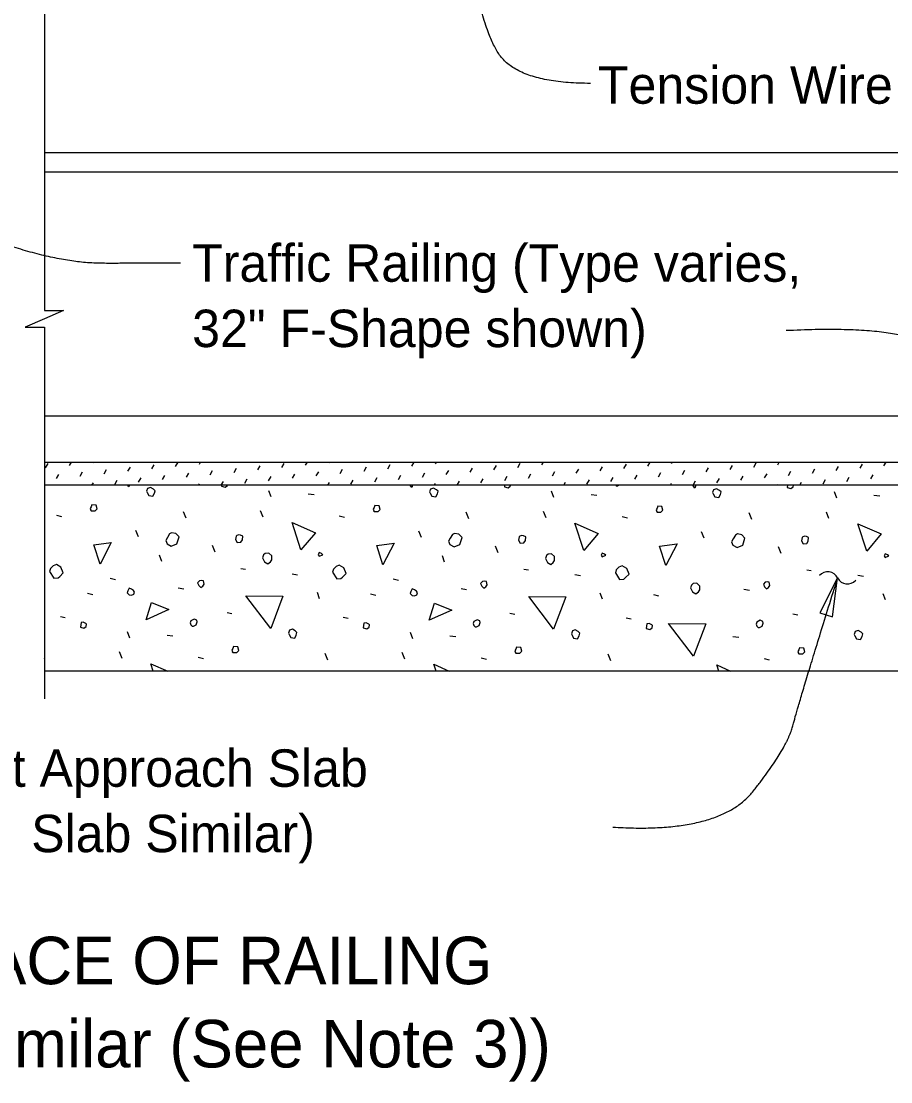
# Model space of a CAD drawing. Extents: x 0 to 41.1, y 0 to 25.9.
# Drawn here: x 16.13 to 20.81, y 11.22 to 16.93 of the extents above; entities that cross this region are included whole.
import ezdxf

# ---------------------------------------------------------------- set-up
doc = ezdxf.new("R2010")
doc.units = 0
for name, color, linetype in [('Dimension', 7, 'Continuous'), ('Miscellaneous', 7, 'Continuous'), ('SupstrConc', 7, 'Continuous'), ('SupstrConc_h', 7, 'Continuous'), ('TextStructures', 7, 'Continuous')]:
    doc.layers.add(name, color=color, linetype=linetype)

msp = doc.modelspace()

# ---------------------------------------------------------------- linework, layer by layer
at = {"layer": 'Dimension'}
msp.add_lwpolyline([(16.252, 17.2246), (16.252, 15.3737), (16.3553, 15.3737), (16.252, 15.3287), (16.1487, 15.2837), (16.252, 15.2837), (16.252, 13.2829)], dxfattribs=at)
msp.add_lwpolyline([(20.5246, 13.9338), (20.4289, 13.7455), (20.4962, 13.7245)], close=True, dxfattribs=at)
for centre, start, end in [((20.4706, 13.907), 26.8413, 138.5686), ((20.577, 13.9608), 206.8413, 318.5686)]:
    msp.add_arc(centre, 0.0596, start, end, dxfattribs=at)
for points in [[(19.1927, 16.5972), (18.7949, 16.5972), (18.5909, 16.9342), (18.5297, 17.3911)], [(16.9853, 15.6282), (16.9154, 15.6282), (16.2159, 15.6282), (15.6583, 15.8852)], [(20.2473, 15.2675), (20.836, 15.2958), (21.1574, 15.0877), (21.234, 15.0765)], [(19.3131, 12.5922), (19.886, 12.5557), (20.2509, 13.0124), (20.3172, 13.2697), (20.5245, 13.9337)]]:
    msp.add_open_spline(points, degree=2, dxfattribs=at)
at = {"layer": 'Miscellaneous'}
for p, q in [((16.2587, 14.5271), (16.2717, 14.5495)), ((16.3872, 14.5401), (16.3975, 14.5578)), ((16.5157, 14.5531), (16.5184, 14.5578)), ((16.5734, 14.4953), (16.5864, 14.5177)), ((16.7019, 14.5083), (16.7148, 14.5307)), ((16.8303, 14.5212), (16.8433, 14.5436)), ((16.9588, 14.5342), (16.9717, 14.5566)), ((17.0872, 14.5472), (17.0934, 14.5578)), ((17.145, 14.4894), (17.1579, 14.5118)), ((17.2734, 14.5024), (17.2864, 14.5248)), ((17.4019, 14.5154), (17.4149, 14.5377)), ((17.5303, 14.5283), (17.5433, 14.5507)), ((17.6588, 14.5413), (17.6684, 14.5578)), ((17.7873, 14.5542), (17.7893, 14.5578)), ((17.845, 14.4965), (17.858, 14.5189)), ((17.9735, 14.5095), (17.9864, 14.5318)), ((18.1019, 14.5224), (18.1149, 14.5448)), ((18.2304, 14.5354), (18.2433, 14.5578)), ((18.3588, 14.5483), (18.3643, 14.5578)), ((18.4166, 14.4906), (18.4296, 14.513)), ((18.545, 14.5036), (18.558, 14.526)), ((18.6735, 14.5165), (18.6865, 14.5389)), ((18.802, 14.5295), (18.8149, 14.5519)), ((18.9304, 14.5425), (18.9393, 14.5578)), ((18.9882, 14.4847), (19.0011, 14.5071)), ((19.0589, 14.5554), (19.0603, 14.5578)), ((19.1166, 14.4977), (19.1296, 14.5201)), ((19.2451, 14.5106), (19.258, 14.533)), ((19.3735, 14.5236), (19.3865, 14.546)), ((19.502, 14.5366), (19.5143, 14.5578)), ((19.6305, 14.5495), (19.6353, 14.5578)), ((19.6882, 14.4918), (19.7012, 14.5142)), ((19.8167, 14.5047), (19.8296, 14.5271)), ((19.9451, 14.5177), (19.9581, 14.5401)), ((20.0736, 14.5307), (20.0865, 14.5531)), ((20.202, 14.5436), (20.2103, 14.5578)), ((20.2598, 14.4859), (20.2727, 14.5083)), ((20.3305, 14.5566), (20.3312, 14.5578)), ((20.3882, 14.4989), (20.4012, 14.5212)), ((20.5167, 14.5118), (20.5297, 14.5342)), ((20.6452, 14.5248), (20.6581, 14.5472)), ((20.7736, 14.5377), (20.7852, 14.5578)), ((16.3165, 14.4694), (16.3294, 14.4918)), ((16.4449, 14.4824), (16.4579, 14.5047)), ((16.6311, 14.4376), (16.6441, 14.46)), ((16.7596, 14.4505), (16.7726, 14.4729)), ((16.8881, 14.4635), (16.901, 14.4859)), ((17.0165, 14.4765), (17.0295, 14.4989)), ((17.2034, 14.4329), (17.2157, 14.4541)), ((17.3312, 14.4446), (17.3441, 14.467)), ((17.4596, 14.4576), (17.4726, 14.48)), ((17.5881, 14.4706), (17.6011, 14.493)), ((17.7166, 14.4835), (17.7295, 14.5059)), ((17.9028, 14.4387), (17.9157, 14.4611)), ((18.0312, 14.4517), (18.0442, 14.4741)), ((18.1597, 14.4647), (18.1726, 14.4871)), ((18.2881, 14.4776), (18.3011, 14.5)), ((18.4743, 14.4329), (18.4873, 14.4552)), ((18.6028, 14.4458), (18.6158, 14.4682)), ((18.7313, 14.4588), (18.7442, 14.4812)), ((18.8597, 14.4717), (18.8727, 14.4941)), ((19.0493, 14.4329), (19.0589, 14.4494)), ((19.1744, 14.4399), (19.1873, 14.4623)), ((19.3028, 14.4529), (19.3158, 14.4753)), ((19.4313, 14.4659), (19.4443, 14.4882)), ((19.5597, 14.4788), (19.5727, 14.5012)), ((19.746, 14.434), (19.7589, 14.4564)), ((19.8744, 14.447), (19.8874, 14.4694)), ((20.0029, 14.46), (20.0158, 14.4824)), ((20.1313, 14.4729), (20.1443, 14.4953)), ((20.3203, 14.4329), (20.3305, 14.4505)), ((20.446, 14.4411), (20.459, 14.4635)), ((20.5744, 14.4541), (20.5874, 14.4765)), ((20.7029, 14.467), (20.7159, 14.4894)), ((16.5075, 14.4329), (16.5157, 14.447)), ((17.0825, 14.4329), (17.0872, 14.4411)), ((17.4727, 14.3704), (17.4603, 14.404)), ((17.6574, 14.4329), (17.6588, 14.4352)), ((17.7784, 14.4329), (17.7873, 14.4482)), ((18.3534, 14.4329), (18.3588, 14.4423)), ((18.9965, 14.3669), (18.9841, 14.4005)), ((19.6243, 14.4329), (19.6305, 14.4435)), ((20.1993, 14.4329), (20.202, 14.4376)), ((20.5203, 14.3634), (20.508, 14.397)), ((17.6725, 14.3864), (17.7043, 14.3828)), ((19.1963, 14.3828), (19.2281, 14.3793)), ((20.7201, 14.3793), (20.7519, 14.3757)), ((17.0148, 14.2555), (17.0007, 14.2909)), ((17.4303, 14.2608), (17.4161, 14.2962)), ((18.5387, 14.252), (18.5245, 14.2874)), ((18.9541, 14.2573), (18.9399, 14.2927)), ((20.0625, 14.2485), (20.0483, 14.2838)), ((20.4779, 14.2538), (20.4638, 14.2891)), ((16.3166, 14.2715), (16.3449, 14.2644)), ((17.8404, 14.2679), (17.8687, 14.2608)), ((19.3642, 14.2644), (19.3925, 14.2573)), ((16.7585, 14.1548), (16.7444, 14.1901)), ((18.2823, 14.1512), (18.2682, 14.1866)), ((19.8062, 14.1477), (19.792, 14.1831)), ((17.1722, 14.0735), (17.158, 14.1088)), ((16.884, 14.0222), (16.8717, 14.0558)), ((18.4078, 14.0187), (18.3955, 14.0522)), ((18.696, 14.0699), (18.6819, 14.1053)), ((20.2198, 14.0664), (20.2057, 14.1017)), ((17.3101, 13.9851), (17.3348, 13.9815)), ((17.5858, 13.9568), (17.6159, 13.9515)), ((18.8339, 13.9815), (18.8586, 13.978)), ((19.1097, 13.9533), (19.1397, 13.948)), ((20.3577, 13.978), (20.3824, 13.9745)), ((20.6335, 13.9497), (20.6635, 13.9444)), ((16.6065, 13.932), (16.6348, 13.925)), ((16.9724, 13.8808), (17.0025, 13.8755)), ((18.1303, 13.9285), (18.1586, 13.9214)), ((16.4845, 13.8525), (16.5128, 13.8454)), ((17.7343, 13.8224), (17.722, 13.856)), ((18.0083, 13.849), (18.0366, 13.8419)), ((18.4962, 13.8772), (18.5263, 13.8719)), ((19.2581, 13.8189), (19.2458, 13.8525)), ((19.5321, 13.8454), (19.5604, 13.8383)), ((20.0201, 13.8737), (20.0501, 13.8684)), ((20.782, 13.8154), (20.7696, 13.849)), ((16.3378, 13.727), (16.3643, 13.7217)), ((17.2358, 13.7482), (17.2623, 13.7429)), ((17.8616, 13.7234), (17.8881, 13.7181)), ((18.7596, 13.7447), (18.7862, 13.7394)), ((19.3854, 13.7199), (19.4119, 13.7146)), ((20.2834, 13.7411), (20.31, 13.7358)), ((16.7126, 13.6103), (16.7002, 13.6439)), ((16.9123, 13.6262), (16.9441, 13.6227)), ((18.2364, 13.6068), (18.224, 13.6404)), ((18.4361, 13.6227), (18.468, 13.6191)), ((19.9599, 13.6191), (19.9918, 13.6156)), ((16.6701, 13.5007), (16.656, 13.5361)), ((16.2547, 13.4954), (16.252, 13.5023)), ((17.0803, 13.5078), (17.1085, 13.5007)), ((17.7785, 13.4919), (17.7644, 13.5272)), ((18.1939, 13.4972), (18.1798, 13.5325)), ((18.6041, 13.5042), (18.6324, 13.4972)), ((19.3023, 13.4883), (19.2882, 13.5237)), ((20.1279, 13.5007), (20.1562, 13.4936))]:
    msp.add_line(p, q, dxfattribs=at)
for points in [[(16.7073, 14.4252), (16.7015, 14.4329)], [(16.7101, 14.4329), (16.7073, 14.4252)], [(16.8063, 14.3934), (16.8151, 14.3775), (16.8363, 14.374), (16.8451, 14.3899), (16.8487, 14.404), (16.8398, 14.4129), (16.8239, 14.4217), (16.808, 14.4164), (16.8027, 14.4005), (16.8063, 14.3934)], [(17.2058, 14.4288), (17.2252, 14.4235), (17.2376, 14.4323), (17.2377, 14.4329)], [(17.2063, 14.4329), (17.2058, 14.4288)], [(18.2311, 14.4217), (18.2226, 14.4329)], [(18.2352, 14.4329), (18.2311, 14.4217)], [(18.3301, 14.3899), (18.3389, 14.374), (18.3601, 14.3704), (18.369, 14.3864), (18.3725, 14.4005), (18.3637, 14.4093), (18.3477, 14.4182), (18.3318, 14.4129), (18.3265, 14.397), (18.3301, 14.3899)], [(18.7296, 14.4252), (18.749, 14.4199), (18.7614, 14.4288), (18.762, 14.4329)], [(18.7307, 14.4329), (18.7296, 14.4252)], [(19.3301, 14.4329), (19.3324, 14.4306)], [(19.3324, 14.4306), (19.3395, 14.4306), (19.3441, 14.4329)], [(19.7549, 14.4182), (19.7437, 14.4329)], [(19.7604, 14.4329), (19.7549, 14.4182)], [(19.8539, 14.3864), (19.8627, 14.3704), (19.8839, 14.3669), (19.8928, 14.3828), (19.8963, 14.397), (19.8875, 14.4058), (19.8716, 14.4146), (19.8556, 14.4093), (19.8503, 14.3934), (19.8539, 14.3864)], [(20.2534, 14.4217), (20.2728, 14.4164), (20.2852, 14.4252), (20.2863, 14.4329)], [(20.255, 14.4329), (20.2534, 14.4217)], [(16.504, 14.2962), (16.5252, 14.2962), (16.5358, 14.3068), (16.5305, 14.3263), (16.5075, 14.328), (16.504, 14.3174), (16.4987, 14.3086), (16.504, 14.2962), (16.5004, 14.2997)], [(18.0278, 14.2927), (18.049, 14.2927), (18.0596, 14.3033), (18.0543, 14.3227), (18.0313, 14.3245), (18.0278, 14.3139), (18.0225, 14.305), (18.0278, 14.2927), (18.0242, 14.2962)], [(19.5516, 14.2891), (19.5728, 14.2891), (19.5834, 14.2997), (19.5781, 14.3192), (19.5551, 14.3209), (19.5516, 14.3103), (19.5463, 14.3015), (19.5516, 14.2891), (19.5481, 14.2927)], [(17.6336, 14.0858), (17.5858, 14.2326), (17.7113, 14.1778), (17.6336, 14.0858)], [(19.1574, 14.0823), (19.1097, 14.229), (19.2352, 14.1742), (19.1574, 14.0823)], [(20.6812, 14.0788), (20.6335, 14.2255), (20.759, 14.1707), (20.6812, 14.0788)], [(16.9123, 14.1177), (16.9353, 14.1053), (16.9654, 14.1177), (16.9777, 14.1548), (16.96, 14.1725), (16.9371, 14.1778), (16.9265, 14.1707), (16.9141, 14.1512), (16.9052, 14.1353), (16.9123, 14.1177)], [(17.2818, 14.1406), (17.2906, 14.1247), (17.3101, 14.1265), (17.3189, 14.1389), (17.3207, 14.1583), (17.3083, 14.1636), (17.2995, 14.1654), (17.2889, 14.1619), (17.2853, 14.1583), (17.2818, 14.1406)], [(18.4361, 14.1141), (18.4591, 14.1017), (18.4892, 14.1141), (18.5015, 14.1512), (18.4839, 14.1689), (18.4609, 14.1742), (18.4503, 14.1672), (18.4379, 14.1477), (18.4291, 14.1318), (18.4361, 14.1141)], [(19.9599, 14.1106), (19.9829, 14.0982), (20.013, 14.1106), (20.0254, 14.1477), (20.0077, 14.1654), (19.9847, 14.1707), (19.9741, 14.1636), (19.9617, 14.1442), (19.9529, 14.1283), (19.9599, 14.1106)], [(16.5517, 14.0081), (16.5181, 14.1124), (16.6118, 14.1247), (16.5517, 14.0081)], [(18.0755, 14.0045), (18.0419, 14.1088), (18.1356, 14.1212), (18.0755, 14.0045)], [(18.8056, 14.1371), (18.8144, 14.1212), (18.8339, 14.123), (18.8427, 14.1353), (18.8445, 14.1548), (18.8321, 14.1601), (18.8233, 14.1619), (18.8127, 14.1583), (18.8091, 14.1548), (18.8056, 14.1371)], [(19.5993, 14.001), (19.5657, 14.1053), (19.6594, 14.1177), (19.5993, 14.001)], [(20.3294, 14.1336), (20.3382, 14.1177), (20.3577, 14.1194), (20.3665, 14.1318), (20.3683, 14.1512), (20.3559, 14.1565), (20.3471, 14.1583), (20.3365, 14.1548), (20.3329, 14.1512), (20.3294, 14.1336)], [(17.4267, 14.0416), (17.4373, 14.0204), (17.455, 14.0098), (17.4692, 14.0204), (17.4762, 14.031), (17.4762, 14.0522), (17.4603, 14.0682), (17.4409, 14.0664), (17.432, 14.0576), (17.4267, 14.0416)], [(17.7326, 14.0505), (17.752, 14.0593), (17.7449, 14.0664), (17.7326, 14.0717), (17.7273, 14.0593), (17.7326, 14.0505)], [(18.9506, 14.0381), (18.9612, 14.0169), (18.9788, 14.0063), (18.993, 14.0169), (19.0001, 14.0275), (19.0001, 14.0487), (18.9841, 14.0646), (18.9647, 14.0629), (18.9559, 14.054), (18.9506, 14.0381)], [(19.2564, 14.0469), (19.2758, 14.0558), (19.2688, 14.0629), (19.2564, 14.0682), (19.2511, 14.0558), (19.2564, 14.0469)], [(20.7802, 14.0434), (20.7996, 14.0522), (20.7926, 14.0593), (20.7802, 14.0646), (20.7749, 14.0522), (20.7802, 14.0434)], [(16.2795, 13.9692), (16.3024, 13.932), (16.3254, 13.9338), (16.3343, 13.9426), (16.3537, 13.9621), (16.3413, 13.9921), (16.3166, 14.0063), (16.2989, 13.9992), (16.2848, 13.9851), (16.2795, 13.9692)], [(17.8033, 13.9656), (17.8263, 13.9285), (17.8492, 13.9303), (17.8581, 13.9391), (17.8775, 13.9586), (17.8651, 13.9886), (17.8404, 14.0028), (17.8227, 13.9957), (17.8086, 13.9815), (17.8033, 13.9656)], [(19.3271, 13.9621), (19.3501, 13.925), (19.373, 13.9267), (19.3819, 13.9356), (19.4013, 13.955), (19.389, 13.9851), (19.3642, 13.9992), (19.3465, 13.9921), (19.3324, 13.978), (19.3271, 13.9621)], [(16.709, 13.8437), (16.7214, 13.8419), (16.7338, 13.8472), (16.7373, 13.8578), (16.732, 13.8666), (16.7214, 13.8737), (16.709, 13.879), (16.702, 13.8649), (16.6984, 13.8543), (16.709, 13.8437)], [(17.0838, 13.8931), (17.0944, 13.8825), (17.105, 13.8896), (17.1121, 13.9002), (17.1085, 13.9179), (17.0997, 13.9197), (17.0873, 13.9179), (17.0767, 13.9073), (17.0838, 13.8931)], [(18.6076, 13.8896), (18.6182, 13.879), (18.6288, 13.8861), (18.6359, 13.8967), (18.6324, 13.9144), (18.6235, 13.9161), (18.6111, 13.9144), (18.6005, 13.9038), (18.6076, 13.8896)], [(19.7325, 13.8799), (19.7431, 13.8587), (19.7608, 13.8481), (19.7749, 13.8587), (19.782, 13.8693), (19.782, 13.8905), (19.7661, 13.9064), (19.7467, 13.9047), (19.7378, 13.8958), (19.7325, 13.8799)], [(20.1314, 13.8861), (20.142, 13.8755), (20.1526, 13.8825), (20.1597, 13.8931), (20.1562, 13.9108), (20.1473, 13.9126), (20.135, 13.9108), (20.1244, 13.9002), (20.1314, 13.8861)], [(17.4709, 13.6616), (17.3366, 13.8383), (17.5363, 13.8366), (17.4709, 13.6616)], [(18.2328, 13.8401), (18.2452, 13.8383), (18.2576, 13.8437), (18.2611, 13.8543), (18.2558, 13.8631), (18.2452, 13.8702), (18.2328, 13.8755), (18.2258, 13.8613), (18.2222, 13.8507), (18.2328, 13.8401)], [(18.9947, 13.658), (18.8604, 13.8348), (19.0602, 13.833), (18.9947, 13.658)], [(16.8009, 13.7093), (16.8292, 13.8012), (16.9229, 13.7641), (16.8009, 13.7093)], [(18.3248, 13.7058), (18.353, 13.7977), (18.4467, 13.7606), (18.3248, 13.7058)], [(17.0484, 13.6739), (17.0555, 13.6739), (17.0696, 13.681), (17.075, 13.6969), (17.0732, 13.7058), (17.059, 13.7128), (17.0414, 13.7022), (17.0378, 13.6916), (17.0414, 13.681), (17.0484, 13.6739)], [(18.5723, 13.6704), (18.5793, 13.6704), (18.5935, 13.6775), (18.5988, 13.6934), (18.597, 13.7022), (18.5829, 13.7093), (18.5652, 13.6987), (18.5616, 13.6881), (18.5652, 13.6775), (18.5723, 13.6704)], [(16.4456, 13.6686), (16.4651, 13.6633), (16.4774, 13.6722), (16.4792, 13.6846), (16.4757, 13.6881), (16.4615, 13.6952), (16.4492, 13.6934), (16.4474, 13.681), (16.4456, 13.6686)], [(17.5699, 13.6298), (17.5788, 13.6138), (17.6, 13.6103), (17.6088, 13.6262), (17.6124, 13.6404), (17.6035, 13.6492), (17.5876, 13.658), (17.5717, 13.6527), (17.5664, 13.6368), (17.5699, 13.6298)], [(17.9694, 13.6651), (17.9889, 13.6598), (18.0013, 13.6686), (18.003, 13.681), (17.9995, 13.6846), (17.9854, 13.6916), (17.973, 13.6899), (17.9712, 13.6775), (17.9694, 13.6651)], [(19.0937, 13.6262), (19.1026, 13.6103), (19.1238, 13.6068), (19.1326, 13.6227), (19.1362, 13.6368), (19.1273, 13.6457), (19.1114, 13.6545), (19.0955, 13.6492), (19.0902, 13.6333), (19.0937, 13.6262)], [(19.4933, 13.6616), (19.5127, 13.6563), (19.5251, 13.6651), (19.5268, 13.6775), (19.5233, 13.681), (19.5092, 13.6881), (19.4968, 13.6863), (19.495, 13.6739), (19.4933, 13.6616)], [(19.7486, 13.5127), (19.6143, 13.6895), (19.814, 13.6877), (19.7486, 13.5127)], [(20.0961, 13.6669), (20.1031, 13.6669), (20.1173, 13.6739), (20.1226, 13.6899), (20.1208, 13.6987), (20.1067, 13.7058), (20.089, 13.6952), (20.0855, 13.6846), (20.089, 13.6739), (20.0961, 13.6669)], [(20.6176, 13.6227), (20.6264, 13.6068), (20.6476, 13.6032), (20.6564, 13.6191), (20.66, 13.6333), (20.6511, 13.6421), (20.6352, 13.651), (20.6193, 13.6457), (20.614, 13.6298), (20.6176, 13.6227)], [(17.2676, 13.5325), (17.2889, 13.5325), (17.2995, 13.5431), (17.2942, 13.5626), (17.2712, 13.5643), (17.2676, 13.5537), (17.2623, 13.5449), (17.2676, 13.5325), (17.2641, 13.5361)], [(18.7915, 13.529), (18.8127, 13.529), (18.8233, 13.5396), (18.818, 13.559), (18.795, 13.5608), (18.7915, 13.5502), (18.7862, 13.5414), (18.7915, 13.529), (18.7879, 13.5325)], [(20.3153, 13.5255), (20.3365, 13.5255), (20.3471, 13.5361), (20.3418, 13.5555), (20.3188, 13.5573), (20.3153, 13.5467), (20.31, 13.5378), (20.3153, 13.5255), (20.3117, 13.529)], [(16.8386, 13.4328), (16.8257, 13.4724), (16.9163, 13.4328)], [(18.3612, 13.4329), (18.3495, 13.4689), (18.432, 13.4329)], [(19.8839, 13.4329), (19.8733, 13.4653), (19.9477, 13.4329)]]:
    msp.add_lwpolyline(points, dxfattribs=at)
at = {"layer": 'SupstrConc'}
for p, q in [((16.252, 16.2245), (23.5538, 16.2245)), ((16.252, 16.1203), (23.5538, 16.1203)), ((16.252, 14.5578), (23.5538, 14.5578)), ((21.5538, 14.4329), (16.252, 14.4329)), ((21.9365, 13.4328), (16.252, 13.4328))]:
    msp.add_line(p, q, dxfattribs=at)
at = {"layer": 'SupstrConc_h'}
msp.add_line((16.252, 14.8078), (23.5538, 14.8078), dxfattribs=at)

# ---------------------------------------------------------------- texts
at = {"layer": 'Dimension'}
for s, height, p in [('Traffic Railing (Type varies,', 0.2016, (17.0479, 15.5291)), ('32" F-Shape shown)', 0.2016, (17.0479, 15.1771)), ('Approach Slab (Flexible Pavement Approach Slab ', 0.2016, (11.9999, 12.8093)), ('Shown, Rigid Pavement Approach Slab Similar)', 0.2016, (11.9999, 12.4573)), ('ELEVATION OF OUTSIDE FACE OF RAILING', 0.256001, (11.5134, 11.7461)), ('(Traffic Railing Shown, Concrete Parapet Similar (See Note 3))', 0.256001, (9.4668, 11.2981))]:
    msp.add_text(s, height=height, dxfattribs=at).set_placement(p)
at = {"layer": 'TextStructures'}
msp.add_text('Tension Wire', height=0.2016, dxfattribs=at).set_placement((19.2335, 16.4877))

doc.saveas('drawing.dxf')
